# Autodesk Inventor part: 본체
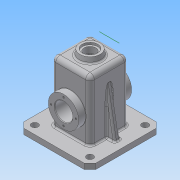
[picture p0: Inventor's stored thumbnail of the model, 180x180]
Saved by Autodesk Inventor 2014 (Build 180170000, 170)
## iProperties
Created: 2016-02
Part Number: 본체
Material: Generic
Document SubType Name: Modeling
Designer: User
Density: 1 g/cm^3
Appearance: Default
Author: User
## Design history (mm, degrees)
sketch "스케치1"
  geometry: L1 (-35, 35)-(35, 35); L2 (35, 35)-(35, -35); L3 (35, -35)-(-35, -35); L4 (-35, -35)-(-35, 35); 3 further points
  constraints: 8 end point, 2 midpoint, 2 parallel, 1 horizontal, 1 horizontal alignment, 1 perpendicular, 1 vertical alignment
  dimensions: "d0" = 70 distance of L1.start L1.end; "d1" = 70 distance of L1.end L2.end
extrude "돌출1" new body sketch "스케치1" distance "d2" = 120; taper "d3" = 0 deg
feature "쉘1" dims "d4" = 5
sketch "스케치2"
  geometry: L1 (35, 35)-(-35, 35) reference; L2 (-35, 35)-(-35, -35) reference; L3 (-35, -35)-(35, -35) reference; L4 (35, -35)-(35, 35) reference; L5 (-65, 65)-(65, 65); L6 (65, 65)-(65, -65); L7 (65, -65)-(-65, -65); L8 (-65, -65)-(-65, 65); 3 further points
  constraints: 8 end point, 2 midpoint, 2 parallel, 1 horizontal, 1 horizontal alignment, 1 perpendicular, 1 vertical alignment
  dimensions: "d5" = 130 distance of L5.start L5.end; "d6" = 130 distance of L7.end L5.start
extrude "돌출2" join sketch "스케치2" distance "d7" = 10; taper "d8" = 0 deg
sketch "스케치3"
  geometry: L1 (-56.992, 55)-(56.992, 55); L2 (-23, 55)-(-23, 75.5); L3 (-23, 75.5)-(-30, 82.5); L4 (30, 0)-(30, 115) reference; L5 (30, 115)-(-30, 115) reference; L6 (-30, 115)-(-30, 0) reference; L7 (-30, 0)-(-65, 0) reference; L8 (-65, 0)-(-65, 10) reference; L9 (-65, 10)-(-35, 10) reference; L10 (-35, 10)-(-35, 120) reference; L11 (-35, 120)-(35, 120) reference; L12 (35, 120)-(35, 10) reference; L13 (35, 10)-(65, 10) reference; L14 (65, 10)-(65, 0) reference; L15 (65, 0)-(30, 0) reference; L16 (-23, 55)-(-30, 55); L17 (-30, 55)-(-30, 82.5); 1 further point
  constraints: 10 end point, 4 point on line, 1 horizontal, 1 perpendicular
  dimensions: "d9" = 55 distance from line of point (0, 0) L1; "d10" = 55 diameter of L3.end L1; "d11" = 7 distance between parallel lines of L17 L2; "d12" = 135 deg angle of L3 L6
revolve "회전1" sketch "스케치3" stored, may be unused: angle "d13" = 90 deg
sketch "스케치4"
  geometry: L1 (-30, -120)-(100, -120) reference; C1 r 27.5 at (35, -65); 2 further points
  constraints: 1 centre point, 1 midpoint, 1 vertical alignment
  dimensions: "d14" = 55 distance from line of L1 C1.centre; "d15" = 55 diameter of C1
extrude "돌출3" join sketch "스케치4" distance "d16" = 13; taper "d17" = 0 deg
hole "구멍1" diameter "d20" = 32; stored, may be unused: countersink angle "d24" = 90 deg, drill point angle "d26" = 0 deg; dims "d18" = 10, "d19" = 10, "d21" = 6, "d22" = 4, "d23" = 2, "d25" = 30
hole "구멍2" diameter "d29" = 32; stored, may be unused: countersink angle "d33" = 90 deg, drill point angle "d35" = 0 deg; dims "d27" = 10, "d28" = 10, "d30" = 6, "d31" = 4, "d32" = 2, "d34" = 30
node "작업 평면1"
sketch "스케치5"
  geometry: C1 r 20 at (0, 0); 1 further point
  constraints: 1 centre point, 1 coincident
  dimensions: "d37" = 40 diameter of C1
extrude "돌출4" join sketch "스케치5" stored distance "d38" = 13; taper "d39" = 0 deg
hole "구멍3" diameter "d42" = 21; stored, may be unused: countersink angle "d46" = 90 deg, drill point angle "d48" = 0 deg; dims "d40" = 10, "d41" = 10, "d43" = 6, "d44" = 28, "d45" = 4, "d47" = 30
chamfer "모따기1" distance "d49" = 10; stored, may be unused: second distance "d50" = 2, angle "d51" = 45 deg
chamfer "모따기2" distance "d52" = 10; stored, may be unused: second distance "d53" = 2, angle "d54" = 10 deg
sketch "스케치6"
  geometry: L1 (-14, 126)-(-10.5, 126) reference; L2 (-10.5, 126)-(-10.5, 115) reference; L3 (-10.5, 115)-(-30, 115) reference; L4 (-30, 115)-(-30, 0) reference; L5 (-30, 0)-(-65, 0) reference; L6 (-65, 0)-(-65, 10) reference; L7 (-65, 10)-(-35, 10) reference; L8 (-35, 10)-(-35, 120) reference; L9 (-35, 120)-(-20, 120) reference; L10 (-20, 120)-(-18.237, 130) reference; L11 (-18.237, 130)-(-14, 130) reference; L12 (-14, 130)-(-14, 126) reference; L13 (10.5, 126)-(14, 126) reference; L14 (14, 126)-(14, 130) reference; L15 (14, 130)-(18.237, 130) reference; L16 (18.237, 130)-(20, 120) reference; L17 (20, 120)-(35, 120) reference; L18 (35, 120)-(35, 10) reference; L19 (35, 10)-(65, 10) reference; L20 (65, 10)-(65, 0) reference; L21 (65, 0)-(30, 0) reference; L22 (30, 0)-(30, 115) reference; L23 (30, 115)-(10.5, 115) reference; L24 (10.5, 115)-(10.5, 126) reference; L25 (-35, 95.069)-(-50, 10); 1 further point
  constraints: 2 end point, 1 midpoint, 1 parallel, 1 point on line
  dimensions: "d55" = 15 distance from line of L6 L25.end
feature "리브1" sketch "스케치6" dims "d56" = 1, "d57" = 10, "d58" = 0, "d59" = 0, "d60" = 1, "d61" = 1
fillet "모깎기1" dims "d62" = 8
fillet "모깎기2" dims "d63" = 8
fillet "모깎기3" dims "d64" = 3
fillet "모깎기4" dims "d65" = 3
fillet "모깎기5" dims "d66" = 3
chamfer "모따기3" distance "d67" = 1; stored, may be unused: second distance "d68" = 2, angle "d69" = 10 deg
sketch "스케치7"
  geometry: L1 (55, 65)-(-55, 65) reference; L2 (-65, 55)-(-65, -55) reference; 2 further points
  dimensions: "d70" = 15 distance from line of L2 point (-50, 50); "d71" = 15 distance from line of L1 point (-50, 50)
hole "구멍4" sketch "스케치7" at (-50, 50) diameter "d72" = 12; stored, may be unused: countersink angle "d76" = 90 deg, drill point angle "d78" = 0 deg; dims "d73" = 6, "d74" = 28, "d75" = 4, "d77" = 30
sketch "스케치8"
  geometry: C1 r 27.5 at (0, 0) reference; 2 further points
  constraints: 1 vertical alignment
  dimensions: "d85" = 22.5 distance of point (0, 22.5) C1.centre
hole "구멍5" sketch "스케치8" at (0, 22.5) diameter "d86" = 3.242; stored, may be unused: countersink angle "d90" = 90 deg, drill point angle "d92" = 118 deg; dims "d87" = 8, "d88" = 28, "d89" = 4, "d91" = 10
fillet "모깎기6" dims "d96" = 3
fillet "모깎기7" dims "d97" = 3
fillet "모깎기8" dims "d98" = 0.5
sketch "스케치11"
  geometry: L1 (27, -57)-(-27, -57) reference; L2 (27, -5.22)-(27, -57) reference; L3 (-27, -57)-(-27, -5.22) reference; L4 (27, -42.5)-(-27, -42.5); L5 (18.237, -75)-(-18.237, -75) reference; A1 r 27.5 centre (0, 0) between (-27, -5.22) and (27, -5.22) reference; 1 further point
  constraints: 2 end point, 2 point on line, 1 horizontal, 1 perpendicular
fillet "모깎기9" dims "d101" = 0.5
sketch "스케치12"
  geometry: L1 (30.573, 35.612)-(97.174, 35.612); L2 (97.174, 35.612)-(97.174, -61.002); L3 (97.174, -61.002)-(30.573, -61.002); L4 (30.573, -61.002)-(30.573, 35.612); 1 further point
  constraints: 8 end point, 2 parallel, 1 horizontal, 1 perpendicular
extrude "돌출5" cut sketch "스케치12" distance "d102" = 90; taper "d103" = 0 deg
node "솔리드1"
mirror "대칭1"
mirror "대칭2"
mirror "대칭3"
pattern_linear "직사각형 패턴1" dims "d81" = 100
pattern_circular "원형 패턴1" dims angle "d94" = 360 deg
mirror "대칭4"
node "절단 모서리 투영1"
node "절단 모서리 투영2"
